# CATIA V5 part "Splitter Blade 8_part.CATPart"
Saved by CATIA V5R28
Part number: Splitter Blade 8_part
Definition: design
Nomenclature: Splitter Blade 8_part
Source: Unknown
Bounding box of the stored display mesh (mm): x -9.895 to -1.408, y -5.169 to -1.92, z 4.237 to 7.742
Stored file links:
  D:\paraturbo-cad\STEP\Turbocompressor_for_Christophe\Splitter Blade 8_part.CATPart
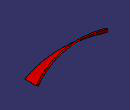
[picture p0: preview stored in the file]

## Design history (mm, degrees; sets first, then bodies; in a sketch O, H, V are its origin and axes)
Body1 "MANIFOLD_SOLID_BREP #75862" (main body)
  Solid1: solid without history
